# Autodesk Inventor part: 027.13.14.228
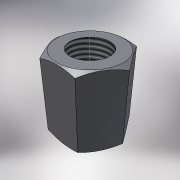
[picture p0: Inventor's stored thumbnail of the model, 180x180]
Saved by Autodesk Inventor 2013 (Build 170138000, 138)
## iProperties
Shininess: 64.0
Length Units: 11269
Angle Units: 11279
Time Units: 11290
Mass Units: 11283
Length Display Precision: 3
Angle Display Precision: 2
Created: 2002-02
Part Number: 027.13.14.228
Material: Steel, Mild
Document SubType Name: Modeling
Designer: SOleg
Density: 7.86 g/cm^3
Density: 0.0
Volumn: 0.0
Area: 0.0
PropertySet Name: Model Information
Control State: 0
Master: False
Checked Out: True
Author: SOleg
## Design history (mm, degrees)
sketch "Sketch1"
  geometry: L1 (9.815, 17)-(19.63, 0); L2 (19.63, 0)-(9.815, -17); L3 (9.815, -17)-(-9.815, -17); L4 (-9.815, -17)-(-19.63, 0); L5 (-19.63, 0)-(-9.815, 17); L6 (-9.815, 17)-(9.815, 17); C1 r 10 at (0, 0); 3 further points
  constraints: 12 end point, 2 coincident, 1 centre point, 1 midpoint, 1 vertical alignment, 13 other
  dimensions: "d1" = 20 diameter of C1
extrude "Extrusion1" new body sketch "Sketch1" distance "d2" = 40; taper "d3" = 0 deg
node "РабОсь1"
sketch "Sketch2"
  geometry: L1 (-16.5, 40)-(-31.416, 40); L2 (0, 45)-(0, -1.383); L3 (-16.5, 40)-(-31.416, 31.388); L4 (-31.416, 31.388)-(-31.416, 40); L5 (17, 0)-(17, 40) reference; L6 (17, 20)-(-24.004, 20); L7 (-16.5, 0)-(-31.416, 0); L8 (-16.5, 0)-(-31.416, 8.612); L9 (-31.416, 8.612)-(-31.416, 0); L10 (0, -10.66)-(0, 54.277) reference; L11 (10, 0)-(-10, 0) reference; L12 (17, 0)-(0, 0) reference; L13 (0, 0)-(-17, 0) reference; L14 (-17, 0)-(0, 0) reference; L15 (0, 0)-(17, 0) reference; L16 (-10, 40)-(10, 40) reference; L17 (17, 40)-(0, 40) reference; L18 (0, 40)-(17, 40) reference; L19 (-17, 40)-(0, 40) reference; L20 (0, 40)-(-17, 40) reference
  constraints: 16 end point, 3 collinear, 3 symmetric about line, 2 perpendicular, 1 midpoint, 3 other
  dimensions: "d5" = 30 deg angle of L1 L3; "d9" = 33 diameter of L7.start L2
revolve "Revolution1" sketch "Sketch2" stored, may be unused: angle "d6" = 90 deg
thread "Thread1" dims "d7" = 10, "d8" = 0
body "Solid1"
node "Спроецированная петля1"
node "Спроецированная петля2"
other parameters: "d0" = 34
